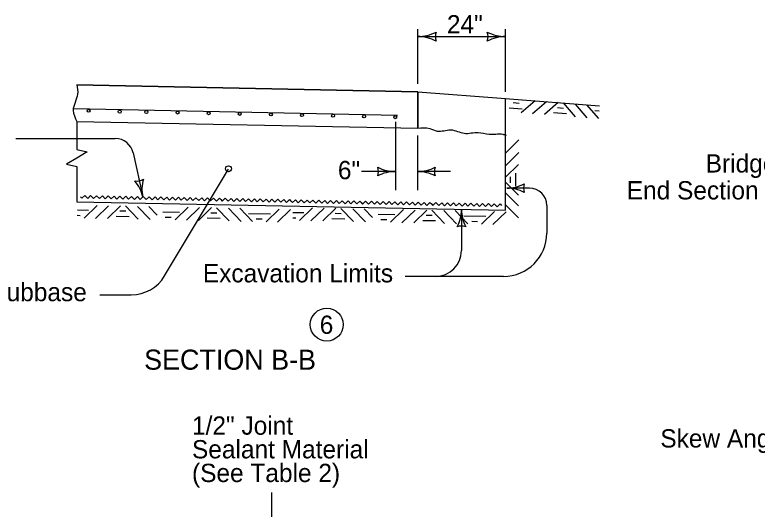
# Model space of a CAD drawing. Extents: x 8925 to 81668, y 4369 to 11918.
# Drawn here: x 17579 to 18391, y 5603 to 6143 of the extents above; entities that cross this region are included whole.
import ezdxf

# ---------------------------------------------------------------- set-up
doc = ezdxf.new("R2010")
doc.units = 0
doc.layers.add('dsnShtPlotShapeBatchPrint', color=7, linetype='Continuous')
doc.layers.add('dsnStdBorder', color=7, linetype='Continuous')

msp = doc.modelspace()

# ---------------------------------------------------------------- linework, layer by layer
at = {"layer": 'dsnShtPlotShapeBatchPrint'}
msp.add_line((17859.95, 5504.21), (17859.95, 5621.11), dxfattribs=at)
at = {"layer": 'dsnStdBorder'}
for p, q in [((18019.57, 6067.95), (18019.57, 6127.65)), ((18115.57, 6059.39), (18115.57, 6127.65)), ((18019.57, 6119.67), (18115.57, 6119.67)), ((18019.57, 6059.39), (17646.65, 6066.87)), ((17646.65, 6066.87), (18019.57, 6059.39)), ((18019.57, 6019.38), (18019.57, 6059.39)), ((18019.57, 6059.39), (18019.57, 6019.38)), ((18019.57, 6059.39), (18115.57, 6052)), ((18114.93, 6052), (18218.39, 6044.04)), ((18115.57, 5929.73), (18115.57, 6051.95)), ((18147.84, 6049.46), (18132.65, 6036.45)), ((18160.24, 6048.28), (18145.05, 6035.27)), ((18173.22, 6047.51), (18158.04, 6034.5)), ((18178.62, 6047.1), (18191.63, 6031.91)), ((18191.57, 6045.87), (18204.59, 6030.69)), ((18204, 6045.14), (18217.02, 6029.96)), ((17696.12, 6039.44), (17642.67, 6040.51)), ((17997.48, 6033.39), (17696.12, 6039.44)), ((17646.64, 6026.6), (17646.64, 5996.34)), ((17646.65, 6026.87), (18019.57, 6019.38)), ((17646.65, 6026.87), (18019.57, 6019.38)), ((17995.57, 5951.84), (17995.57, 6026.31)), ((18019.57, 5951.84), (18019.57, 6011.54)), ((17579.83, 6008.14), (17688.63, 6008.14)), ((18115.8, 5992.62), (18129.94, 6006.77)), ((17646.64, 5996.34), (17657.99, 5993.51)), ((17657.99, 5993.51), (17646.64, 5986.89)), ((17708.16, 5992.44), (17718.77, 5944.31)), ((18115.8, 5978.82), (18129.94, 5992.96)), ((17646.64, 5986.89), (17635.3, 5980.28)), ((17635.3, 5980.28), (17646.64, 5977.44)), ((17646.64, 5977.44), (17646.64, 5939.12)), ((18115.57, 5965.81), (18129.71, 5979.95)), ((17742.62, 5857.99), (17812.43, 5974.77)), ((17994.58, 5972.02), (17958.04, 5972.02)), ((18055.35, 5972.02), (18019.57, 5972.02)), ((17714.38, 5964.23), (17715.5, 5959.13)), ((18115.57, 5960.4), (18129.71, 5946.26)), ((18141.71, 5953.99), (18116.99, 5953.99)), ((18115.57, 5948.83), (18129.71, 5934.68)), ((17646.64, 5939.12), (18115.56, 5929.71)), ((18115.57, 5935.76), (18129.71, 5921.62)), ((17668.91, 5935.11), (17654.49, 5921.25)), ((17681.36, 5934.63), (17666.93, 5920.78)), ((17694.37, 5934.6), (17679.94, 5920.74)), ((17699.78, 5934.49), (17713.63, 5920.06)), ((17712.78, 5934), (17726.63, 5919.58)), ((17725.23, 5933.98), (17734.33, 5924.5)), ((17768.45, 5933.11), (17754.02, 5919.25)), ((17780.89, 5932.63), (17766.47, 5918.78)), ((17793.9, 5932.6), (17779.48, 5918.74)), ((17799.31, 5932.49), (17813.16, 5918.07)), ((17812.31, 5932), (17826.17, 5917.58)), ((17824.76, 5931.98), (17838.62, 5917.56)), ((17867.98, 5931.11), (17853.55, 5917.26)), ((17880.42, 5930.64), (17866, 5916.78)), ((17904.52, 5932.47), (17890.09, 5918.61)), ((17916.96, 5931.99), (17902.54, 5918.14)), ((17929.97, 5931.96), (17915.55, 5918.1)), ((17935.38, 5931.85), (17949.23, 5917.43)), ((17948.38, 5931.36), (17962.24, 5916.94)), ((17960.83, 5931.34), (17969.93, 5921.87)), ((18004.05, 5930.47), (17989.62, 5916.62)), ((18016.49, 5930), (18002.07, 5916.14)), ((18029.5, 5929.96), (18015.08, 5916.11)), ((18034.91, 5929.85), (18048.77, 5915.43)), ((18047.91, 5929.37), (18061.77, 5914.94)), ((18060.36, 5929.34), (18074.22, 5914.92)), ((18067.3, 5930.68), (18067.3, 5885.82)), ((18103.58, 5928.47), (18089.16, 5914.62)), ((18116.02, 5928), (18101.6, 5914.14)), ((18160.61, 5935.09), (18160.61, 5904.73)), ((18113.34, 5857.46), (18005.58, 5857.46)), ((17671.83, 5837.28), (17706.11, 5837.28))]:
    msp.add_line(p, q, dxfattribs=at)
for points in [[(18119.58, 6041.91), (18133.73, 6040.82)], [(18123.85, 6047.45), (18130.36, 6046.95)], [(18172.24, 6042.07), (18178.76, 6041.57)], [(18167.98, 6036.53), (18182.13, 6035.44)], [(18213.14, 6038.95), (18217.97, 6038.58)], [(18126.93, 5956.01), (18126.93, 5970.2)], [(18121.07, 5959.84), (18121.07, 5966.37)], [(17650.45, 5944.45), (17652.02, 5942.82), (17655.29, 5945.96), (17658.42, 5942.69), (17661.68, 5945.83), (17664.82, 5942.56), (17668.08, 5945.7), (17671.22, 5942.44), (17674.48, 5945.57), (17677.62, 5942.31), (17680.88, 5945.44), (17684.02, 5942.18), (17687.28, 5945.31), (17690.41, 5942.05), (17693.68, 5945.19), (17696.81, 5941.92), (17700.08, 5945.06), (17703.21, 5941.79), (17706.48, 5944.93), (17709.61, 5941.66), (17712.87, 5944.8), (17716.01, 5941.54), (17719.27, 5944.67), (17722.41, 5941.41), (17725.67, 5944.54), (17727.24, 5942.91)], [(17727.24, 5942.91), (17728.81, 5941.28), (17732.07, 5944.41), (17735.21, 5941.15), (17738.47, 5944.29), (17741.6, 5941.02), (17744.87, 5944.16), (17748, 5940.89), (17751.27, 5944.03), (17754.4, 5940.77), (17757.67, 5943.9), (17760.8, 5940.64), (17764.06, 5943.77), (17767.2, 5940.51), (17770.46, 5943.64), (17773.6, 5940.38), (17776.86, 5943.52), (17780, 5940.25), (17783.26, 5943.39), (17786.39, 5940.12), (17789.66, 5943.26), (17792.79, 5939.99), (17796.06, 5943.13), (17799.19, 5939.87), (17802.46, 5943), (17804.02, 5941.37)], [(17804.02, 5941.37), (17805.59, 5939.74), (17808.85, 5942.87), (17811.99, 5939.61), (17815.25, 5942.74), (17818.39, 5939.48), (17821.65, 5942.62), (17824.79, 5939.35), (17828.05, 5942.49), (17831.19, 5939.22), (17834.45, 5942.36), (17837.58, 5939.1), (17840.85, 5942.23), (17843.98, 5938.97), (17847.25, 5942.1), (17850.38, 5938.84), (17853.65, 5941.97), (17856.78, 5938.71), (17860.04, 5941.85), (17863.18, 5938.58), (17866.44, 5941.72), (17869.58, 5938.45), (17872.84, 5941.59), (17875.98, 5938.33), (17879.24, 5941.46), (17880.81, 5939.83)], [(17880.84, 5939.73), (17882.41, 5938.1), (17885.67, 5941.23), (17888.81, 5937.97), (17892.07, 5941.1), (17895.21, 5937.84), (17898.47, 5940.97), (17901.61, 5937.71), (17904.87, 5940.85), (17908, 5937.58), (17911.27, 5940.72), (17914.4, 5937.45), (17917.67, 5940.59), (17920.8, 5937.33), (17924.07, 5940.46), (17927.2, 5937.2), (17930.46, 5940.33), (17933.6, 5937.07), (17936.86, 5940.2), (17940, 5936.94), (17943.26, 5940.07), (17946.4, 5936.81), (17949.66, 5939.95), (17952.8, 5936.68), (17956.06, 5939.82), (17957.63, 5938.19)], [(17957.63, 5938.19), (17959.19, 5936.55), (17962.46, 5939.69), (17965.59, 5936.43), (17968.86, 5939.56), (17971.99, 5936.3), (17975.26, 5939.43), (17978.39, 5936.17), (17981.65, 5939.3), (17984.79, 5936.04), (17988.05, 5939.18), (17991.19, 5935.91), (17994.45, 5939.05), (17997.59, 5935.78), (18000.85, 5938.92), (18003.99, 5935.66), (18007.25, 5938.79), (18010.38, 5935.53), (18013.65, 5938.66), (18016.78, 5935.4), (18020.05, 5938.53), (18023.18, 5935.27), (18026.45, 5938.41), (18029.58, 5935.14), (18032.84, 5938.28), (18034.41, 5936.64)], [(18034.41, 5936.64), (18035.98, 5935.01), (18039.24, 5938.15), (18042.38, 5934.88), (18045.64, 5938.02), (18048.78, 5934.76), (18052.04, 5937.89), (18055.18, 5934.63), (18058.44, 5937.76), (18061.57, 5934.5), (18064.84, 5937.63), (18067.97, 5934.37), (18071.24, 5937.51), (18074.37, 5934.24), (18077.63, 5937.38), (18080.77, 5934.11), (18084.03, 5937.25), (18087.17, 5933.99), (18090.43, 5937.12), (18093.57, 5933.86), (18096.83, 5936.99), (18099.97, 5933.73), (18103.23, 5936.86), (18106.36, 5933.6), (18109.63, 5936.74), (18111.2, 5935.1)], [(17647.2, 5930.07), (17659.22, 5929.83)], [(17693.7, 5929.11), (17700.23, 5928.98)], [(17740.69, 5928.19), (17758.76, 5927.83)], [(17882.8, 5927.43), (17894.83, 5927.19)], [(17647.08, 5924.27), (17650.34, 5924.2)], [(17689.75, 5923.33), (17703.94, 5923.05)], [(17743.35, 5922.34), (17749.88, 5922.2)], [(17789.28, 5921.33), (17803.47, 5921.05)], [(17793.23, 5927.11), (17799.76, 5926.98)], [(17834.23, 5926.31), (17858.29, 5925.83)], [(17842.88, 5920.34), (17849.41, 5920.21)], [(17882.68, 5921.63), (17885.94, 5921.57)], [(17925.35, 5920.7), (17939.54, 5920.41)], [(17929.3, 5926.47), (17935.83, 5926.34)], [(17976.3, 5925.55), (17994.36, 5925.19)], [(17978.95, 5919.7), (17985.48, 5919.57)], [(18028.83, 5924.48), (18035.36, 5924.34)], [(18069.83, 5923.68), (18093.89, 5923.19)], [(18024.88, 5918.7), (18039.07, 5918.41)], [(18078.48, 5917.7), (18085.01, 5917.57)]]:
    msp.add_lwpolyline(points, dxfattribs=at)
for centre, radius in [((17659.41, 6038.51), 1.65), ((17693.44, 6037.58), 1.65), ((17722.66, 6037.25), 1.65), ((17756.7, 6036.56), 1.65), ((17790.73, 6035.88), 1.65), ((17824.76, 6035.2), 1.65), ((17858.79, 6034.51), 1.65), ((17892.83, 6033.83), 1.65), ((17926.86, 6033.15), 1.65), ((17960.77, 6032.46), 1.65), ((17994.8, 6031.53), 1.65), ((17812.42, 5975.09), 3.31), ((17919.93, 5804.68), 18)]:
    msp.add_circle(centre, radius, dxfattribs=at)
for centre, radius, start, end in [((18019.57, 6162.17), 42.5, 270, 298.07249), ((18055.21, 6119.67), 16.42, 162.26665, 197.73335), ((18079.94, 6119.67), 16.42, 342.26665, 17.73335), ((18115.57, 6162.17), 42.5, 241.92751, 270), ((18079.94, 6119.67), 16.42, 342.26665, 17.73335), ((18115.57, 6162.17), 42.5, 241.92751, 270), ((18019.57, 6077.17), 42.5, 61.92751, 90), ((18115.57, 6077.17), 42.5, 90, 118.07249), ((18115.57, 6077.17), 42.5, 90, 118.07249), ((17688.63, 5988.14), 20, 12.43134, 90), ((17960.9, 5972.02), 15.52, 342.26665, 17.73335), ((17994.58, 6012.2), 40.18, 241.92751, 270), ((17960.9, 5972.02), 15.52, 342.26665, 17.73335), ((17994.58, 6012.2), 40.18, 241.92751, 270), ((18019.57, 6012.2), 40.18, 270, 298.07249), ((18053.26, 5972.02), 15.52, 162.26665, 197.73335), ((17994.58, 5931.85), 40.18, 90, 118.07249), ((17994.58, 5931.85), 40.18, 90, 118.07249), ((18019.57, 5931.85), 40.18, 61.92751, 90), ((17711.52, 5977.21), 15.52, 264.68499, 300.15169), ((17679.53, 5935.67), 40.18, 12.41834, 40.49083), ((17758, 5952.95), 40.18, 164.34585, 192.41834), ((18116.99, 5994.17), 40.18, 270, 298.07249), ((18116.99, 5994.17), 40.18, 270, 298.07249), ((18116.99, 5913.82), 40.18, 61.92751, 90), ((18116.99, 5913.82), 40.18, 61.92751, 90), ((18150.68, 5953.99), 15.52, 162.26665, 197.73335), ((18150.68, 5953.99), 15.52, 162.26665, 197.73335), ((18141.71, 5935.09), 18.91, 0, 90), ((18027.13, 5930.68), 40.18, 331.92751, 360), ((18107.48, 5930.68), 40.18, 180, 208.07249), ((18067.3, 5896.99), 15.52, 72.26665, 107.73335), ((18113.35, 5904.73), 47.27, 270, 360), ((18038.95, 5885.82), 28.36, 270, 360), ((17706.11, 5879.83), 42.54, 270, 329.12488)]:
    msp.add_arc(centre, radius, start, end, dxfattribs=at)
for points in [[(17646.65, 6066.87), (17647.46, 6056.86), (17642.58, 6038.81), (17646.65, 6026.87)], [(17646.65, 6066.87), (17647.46, 6056.86), (17642.58, 6038.81), (17646.65, 6026.87)], [(18019.57, 6019.38), (18032.52, 6019.17), (18040.65, 6016.3), (18055.47, 6017.73), (18070.3, 6013.91), (18085.6, 6014.87), (18097.56, 6012.95), (18112.39, 6012.95), (18116.21, 6012)]]:
    msp.add_spline(points, degree=3, dxfattribs=at)

# ---------------------------------------------------------------- texts
at = {"layer": 'dsnShtPlotShapeBatchPrint'}
for s, height, p in [('24"', 20, (18051.35, 6123.14)), ('6"', 20, (17932.11, 5963.71)), ('Excavation Limits', 20, (17784.42, 5850.9)), ('Modified Subbase', 20, (17443.4, 5830.31)), ('6', 20, (17912.25, 5794.57)), ('SECTION B-B', 22, (17720.18, 5755.39)), ('1/2" Joint', 20, (17772.53, 5684.32)), ('Skew Angle', 20, (18284.81, 5670.32)), ('Sealant Material', 20, (17772.53, 5658.44)), ('(See Table 2)', 20, (17772.53, 5632.55))]:
    msp.add_text(s, height=height, dxfattribs=at).set_placement(p)
at = {"layer": 'dsnStdBorder'}
for s, p in [('Bridge Rail', (18334.46, 5971.03)), ('End Section (typ.)', (18248.09, 5941.58))]:
    msp.add_text(s, height=20, dxfattribs=at).set_placement(p)

doc.saveas('drawing.dxf')
